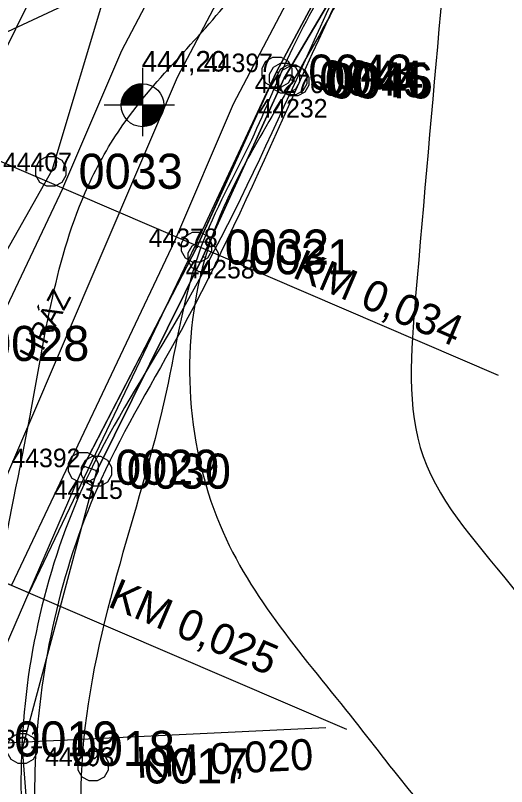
# Model space of a CAD drawing. Extents: x -598521 to -597689, y -1074676 to -1074150.
# Drawn here: x -598484.48 to -598472.57, y -1074197.17 to -1074178.49 of the extents above; entities that cross this region are included whole.
import ezdxf

# ---------------------------------------------------------------- set-up
doc = ezdxf.new("R2010")
doc.units = 0
for name, color, linetype in [('Vrstva 1', 7, 'Continuous'), ('Vrstva 10', 7, 'Continuous'), ('Vrstva 11', 7, 'Continuous'), ('Vrstva 12', 7, 'Continuous'), ('Vrstva 15', 7, 'Continuous'), ('Vrstva 2', 7, 'Continuous'), ('Vrstva 3', 7, 'Continuous'), ('Vrstva 5', 7, 'Continuous'), ('Vrstva 60', 7, 'Continuous'), ('Vrstva 61', 7, 'Continuous'), ('Vrstva 8', 7, 'Continuous')]:
    doc.layers.add(name, color=color, linetype=linetype)

msp = doc.modelspace()

# ---------------------------------------------------------------- linework, layer by layer
at = {"layer": 'Vrstva 1'}
for p, q in [((-598478.16, -1074179.867), (-598478.11, -1074179.867)), ((-598477.98, -1074180.011), (-598477.93, -1074180.011)), ((-598477.799, -1074180.052), (-598477.749, -1074180.052)), ((-598477.751, -1074180.08), (-598477.701, -1074180.08)), ((-598483.642, -1074182.268), (-598483.592, -1074182.268)), ((-598480.11, -1074184.105), (-598480.06, -1074184.105)), ((-598479.949, -1074184.339), (-598479.899, -1074184.339)), ((-598482.856, -1074189.438), (-598482.806, -1074189.438)), ((-598482.536, -1074189.533), (-598482.486, -1074189.533)), ((-598484.337, -1074196.25), (-598484.287, -1074196.25)), ((-598482.62, -1074196.674), (-598482.57, -1074196.674))]:
    msp.add_line(p, q, dxfattribs=at)
for points in [[(-598478.04, -1074179.507), (-598477.87, -1074179.602), (-598477.775, -1074179.772), (-598477.775, -1074179.967), (-598477.87, -1074180.137), (-598478.04, -1074180.232), (-598478.235, -1074180.232), (-598478.405, -1074180.137), (-598478.5, -1074179.967), (-598478.5, -1074179.772), (-598478.405, -1074179.602), (-598478.235, -1074179.507)], [(-598477.86, -1074179.651), (-598477.69, -1074179.746), (-598477.595, -1074179.916), (-598477.595, -1074180.111), (-598477.69, -1074180.281), (-598477.86, -1074180.376), (-598478.055, -1074180.376), (-598478.225, -1074180.281), (-598478.32, -1074180.111), (-598478.32, -1074179.916), (-598478.225, -1074179.746), (-598478.055, -1074179.651)], [(-598477.679, -1074179.692), (-598477.509, -1074179.787), (-598477.414, -1074179.957), (-598477.414, -1074180.152), (-598477.509, -1074180.322), (-598477.679, -1074180.417), (-598477.874, -1074180.417), (-598478.044, -1074180.322), (-598478.139, -1074180.152), (-598478.139, -1074179.957), (-598478.044, -1074179.787), (-598477.874, -1074179.692)], [(-598477.631, -1074179.72), (-598477.461, -1074179.815), (-598477.366, -1074179.985), (-598477.366, -1074180.18), (-598477.461, -1074180.35), (-598477.631, -1074180.445), (-598477.826, -1074180.445), (-598477.996, -1074180.35), (-598478.091, -1074180.18), (-598478.091, -1074179.985), (-598477.996, -1074179.815), (-598477.826, -1074179.72)], [(-598483.522, -1074181.908), (-598483.352, -1074182.003), (-598483.257, -1074182.173), (-598483.257, -1074182.368), (-598483.352, -1074182.538), (-598483.522, -1074182.633), (-598483.717, -1074182.633), (-598483.887, -1074182.538), (-598483.982, -1074182.368), (-598483.982, -1074182.173), (-598483.887, -1074182.003), (-598483.717, -1074181.908)], [(-598479.99, -1074183.745), (-598479.82, -1074183.84), (-598479.725, -1074184.01), (-598479.725, -1074184.205), (-598479.82, -1074184.375), (-598479.99, -1074184.47), (-598480.185, -1074184.47), (-598480.355, -1074184.375), (-598480.45, -1074184.205), (-598480.45, -1074184.01), (-598480.355, -1074183.84), (-598480.185, -1074183.745)], [(-598479.829, -1074183.979), (-598479.659, -1074184.074), (-598479.564, -1074184.244), (-598479.564, -1074184.439), (-598479.659, -1074184.609), (-598479.829, -1074184.704), (-598480.024, -1074184.704), (-598480.194, -1074184.609), (-598480.289, -1074184.439), (-598480.289, -1074184.244), (-598480.194, -1074184.074), (-598480.024, -1074183.979)], [(-598482.736, -1074189.078), (-598482.566, -1074189.173), (-598482.471, -1074189.343), (-598482.471, -1074189.538), (-598482.566, -1074189.708), (-598482.736, -1074189.803), (-598482.931, -1074189.803), (-598483.101, -1074189.708), (-598483.196, -1074189.538), (-598483.196, -1074189.343), (-598483.101, -1074189.173), (-598482.931, -1074189.078)], [(-598482.416, -1074189.173), (-598482.246, -1074189.268), (-598482.151, -1074189.438), (-598482.151, -1074189.633), (-598482.246, -1074189.803), (-598482.416, -1074189.898), (-598482.611, -1074189.898), (-598482.781, -1074189.803), (-598482.876, -1074189.633), (-598482.876, -1074189.438), (-598482.781, -1074189.268), (-598482.611, -1074189.173)], [(-598484.217, -1074195.89), (-598484.047, -1074195.985), (-598483.952, -1074196.155), (-598483.952, -1074196.35), (-598484.047, -1074196.52), (-598484.217, -1074196.615), (-598484.412, -1074196.615), (-598484.582, -1074196.52), (-598484.677, -1074196.35), (-598484.677, -1074196.155), (-598484.582, -1074195.985), (-598484.412, -1074195.89)], [(-598482.5, -1074196.314), (-598482.33, -1074196.409), (-598482.235, -1074196.579), (-598482.235, -1074196.774), (-598482.33, -1074196.944), (-598482.5, -1074197.039), (-598482.695, -1074197.039), (-598482.865, -1074196.944), (-598482.96, -1074196.774), (-598482.96, -1074196.579), (-598482.865, -1074196.409), (-598482.695, -1074196.314)]]:
    msp.add_lwpolyline(points, close=True, dxfattribs=at)
at = {"layer": 'Vrstva 10'}
for points in [[(-598484.92, -1074215.734), (-598487.958, -1074208.491), (-598488.57, -1074195.13), (-598485.971, -1074186.446), (-598483.586, -1074182.241), (-598482.242, -1074177.742), (-598479.451, -1074171.782), (-598475.091, -1074167.2), (-598468.639, -1074162.188), (-598465.635, -1074160.81), (-598454.605, -1074159.518), (-598444.717, -1074161.464), (-598440.447, -1074163.564)], [(-598473.175, -1074171.129), (-598470.76, -1074168.97), (-598466.97, -1074166.72), (-598463.696, -1074165.859), (-598453.096, -1074164.71), (-598446.41, -1074166.04), (-598435.079, -1074171.773), (-598423.335, -1074177.929), (-598417.659, -1074181.967), (-598421.519, -1074188.787), (-598425.53, -1074192.947), (-598427.582, -1074193.806), (-598433.533, -1074199.431), (-598451.678, -1074206.463), (-598460.211, -1074206.905), (-598466.89, -1074208.495), (-598478.904, -1074213.937), (-598483.546, -1074205.944), (-598484.31, -1074196.25), (-598482.504, -1074189.522), (-598479.933, -1074184.345), (-598477.96, -1074180.01), (-598476.52, -1074177.56)], [(-598476.61, -1074175.53), (-598476.74, -1074177.23), (-598478.152, -1074179.86), (-598480.08, -1074184.11), (-598482.83, -1074189.414), (-598485.7, -1074196.02), (-598484.778, -1074206.724), (-598481.095, -1074214.938)], [(-598488.57, -1074195.13), (-598487.78, -1074186.27), (-598487.93, -1074180.4), (-598482.242, -1074177.742)]]:
    msp.add_lwpolyline(points, dxfattribs=at)
msp.add_lwpolyline([(-598476.61, -1074175.53), (-598475.978, -1074175.809), (-598476.52, -1074177.56), (-598477.96, -1074180.01), (-598479.933, -1074184.345), (-598482.504, -1074189.522), (-598482.83, -1074189.414), (-598481.455, -1074186.762), (-598480.08, -1074184.11), (-598479.116, -1074181.985), (-598478.152, -1074179.86), (-598476.74, -1074177.23)], close=True, dxfattribs=at)
at = {"layer": 'Vrstva 11'}
for p, q in [((-598483.334, -1074182.678), (-598487.335, -1074191.113)), ((-598480.623, -1074183.964), (-598484.576, -1074192.297))]:
    msp.add_line(p, q, dxfattribs=at)
at = {"layer": 'Vrstva 12'}
for points in [[(-598477.856, -1074175.904), (-598479.108, -1074177.873), (-598481.873, -1074181.144), (-598482.714, -1074182.62), (-598484.125, -1074188.19), (-598485.335, -1074196.141), (-598485.114, -1074200.364), (-598484.5, -1074206.655), (-598482.536, -1074211.254), (-598480.207, -1074214.488), (-598467.793, -1074210.214), (-598459.725, -1074208.727), (-598453.744, -1074207.761), (-598434.045, -1074202.26), (-598426.944, -1074195.607), (-598420.2, -1074189.398), (-598414.755, -1074180.164), (-598419.159, -1074177.729), (-598424.716, -1074175.666), (-598432.261, -1074171.95), (-598446.273, -1074165.334), (-598449.284, -1074163.066), (-598455.078, -1074161.455), (-598458.605, -1074161.801), (-598464.281, -1074162.718), (-598468.112, -1074164.562), (-598472.279, -1074167.706), (-598475.138, -1074168.205), (-598476.252, -1074168.916), (-598476.978, -1074169.714), (-598477.609, -1074175.205), (-598477.856, -1074175.904)], [(-598473.789, -1074172.039), (-598475.746, -1074175.895), (-598480.673, -1074186.045), (-598482.671, -1074189.544), (-598484.328, -1074196.236), (-598484.11, -1074202.306), (-598483.768, -1074206.314), (-598481.225, -1074209.94), (-598467.357, -1074209.735), (-598459.946, -1074208.147), (-598451.72, -1074206.172), (-598433.884, -1074198.944), (-598427.582, -1074193.806), (-598421.589, -1074188.753), (-598417.664, -1074181.613), (-598423.377, -1074177.475), (-598435.653, -1074170.84), (-598446.227, -1074166.125), (-598452.854, -1074164.125), (-598463.523, -1074165.086), (-598467.1, -1074166.52), (-598468.291, -1074167.262), (-598470.683, -1074168.7), (-598473.219, -1074171.071)], [(-598473.789, -1074172.039), (-598475.746, -1074175.895), (-598480.673, -1074186.045), (-598482.671, -1074189.544), (-598484.328, -1074196.236), (-598484.11, -1074202.306), (-598483.768, -1074206.314), (-598481.225, -1074209.94), (-598467.357, -1074209.735), (-598459.946, -1074208.147), (-598451.72, -1074206.172), (-598433.884, -1074198.944), (-598427.582, -1074193.806), (-598421.589, -1074188.753), (-598417.664, -1074181.613), (-598423.377, -1074177.475), (-598435.653, -1074170.84), (-598446.227, -1074166.125), (-598452.854, -1074164.125), (-598463.523, -1074165.086), (-598467.1, -1074166.52), (-598468.291, -1074167.262), (-598470.683, -1074168.7), (-598473.219, -1074171.071)], [(-598473.448, -1074172.233), (-598475.58, -1074175.922), (-598480.465, -1074186.125), (-598482.4, -1074189.73), (-598483.981, -1074196.229), (-598483.886, -1074202.253), (-598483.546, -1074205.944), (-598480.979, -1074209.161), (-598475.137, -1074210.074), (-598467.043, -1074208.93), (-598460.057, -1074207.659), (-598451.873, -1074205.694), (-598431.777, -1074196.461), (-598429.106, -1074194.199), (-598419.867, -1074184.797), (-598419.874, -1074181.816), (-598423.69, -1074178.164), (-598435.572, -1074171.16), (-598446.402, -1074166.594), (-598452.796, -1074164.414), (-598463.35, -1074165.396), (-598466.975, -1074166.935), (-598468.113, -1074167.583), (-598470.593, -1074168.979), (-598472.889, -1074171.361)], [(-598473.776, -1074172.057), (-598475.787, -1074175.805), (-598476.637, -1074177.247), (-598477.762, -1074179.285), (-598478.759, -1074181.512), (-598479.981, -1074184.111), (-598480.826, -1074187.623), (-598482.872, -1074196.644), (-598480.884, -1074204.447), (-598462.299, -1074205.951), (-598457.621, -1074205.244), (-598448.6, -1074200.236), (-598431.135, -1074190.052), (-598425.671, -1074182.345), (-598436.64, -1074172.436), (-598453.171, -1074165.178), (-598463.86, -1074166.401), (-598467.05, -1074166.63), (-598468.622, -1074167.548), (-598470.002, -1074168.369), (-598470.796, -1074168.897), (-598473.201, -1074171.085)], [(-598473.564, -1074171.726), (-598473.767, -1074172.307), (-598475.013, -1074174.979), (-598476.349, -1074177.568), (-598477.741, -1074180.061), (-598479.834, -1074184.216), (-598479.518, -1074190.843), (-598476.249, -1074195.591), (-598473.028, -1074199.147), (-598469.83, -1074200.65), (-598462.577, -1074200.936), (-598459.26, -1074200.435), (-598452.126, -1074196.474), (-598447.568, -1074189.388), (-598439.169, -1074180.177), (-598437.559, -1074177.648), (-598452.167, -1074170.925), (-598460.9, -1074168.205), (-598465.816, -1074168.205), (-598470.342, -1074169.319), (-598472.087, -1074170.367), (-598473.313, -1074171.425)], [(-598473.564, -1074171.726), (-598474.777, -1074185.291), (-598474.591, -1074189.181), (-598472.32, -1074192.481), (-598469.994, -1074195.048), (-598468.62, -1074195.694), (-598462.854, -1074195.921), (-598460.899, -1074195.626), (-598455.651, -1074192.713), (-598451.546, -1074186.329), (-598444.854, -1074179.795), (-598453.963, -1074175.603), (-598461.661, -1074173.205), (-598473.313, -1074171.425)]]:
    msp.add_spline(points, degree=3, dxfattribs=at)
at = {"layer": 'Vrstva 15'}
for p, q in [((-598472.766, -1074187.213), (-598491.144, -1074179.325)), ((-598476.447, -1074195.791), (-598494.826, -1074187.903)), ((-598476.953, -1074195.75), (-598496.93, -1074196.706))]:
    msp.add_line(p, q, dxfattribs=at)
at = {"layer": 'Vrstva 5'}
for points in [[(-598483.334, -1074182.678), (-598481.903, -1074179.345), (-598476.466, -1074169.022), (-598468.916, -1074163.289), (-598464.703, -1074161.11), (-598455.714, -1074160.021)], [(-598482.963, -1074215.515), (-598486.401, -1074207.525), (-598486.999, -1074195.022), (-598480.548, -1074179.991), (-598475.294, -1074170.015), (-598468.112, -1074164.562), (-598464.254, -1074162.567), (-598455.078, -1074161.455), (-598445.366, -1074162.766), (-598432.996, -1074169.084), (-598417.866, -1074175.801), (-598412.373, -1074178.959)], [(-598480.641, -1074184.01), (-598479.193, -1074180.638), (-598474.122, -1074171.009), (-598467.307, -1074165.835), (-598463.805, -1074164.023), (-598455.361, -1074163)]]:
    msp.add_lwpolyline(points, dxfattribs=at)
at = {"layer": 'Vrstva 60'}
msp.add_lwpolyline([(-598480.179, -1074184.202), (-598480.117, -1074184.058)], dxfattribs=at)
at = {"layer": 'Vrstva 61'}
msp.add_lwpolyline([(-598485.86, -1074181.592), (-598487.335, -1074191.113), (-598484.15, -1074192.479), (-598480.117, -1074184.058), (-598478.152, -1074179.86), (-598476.74, -1074177.23), (-598476.61, -1074175.53), (-598476.12, -1074174.39), (-598475.294, -1074173.013), (-598474.79, -1074172.185), (-598474.564, -1074171.737), (-598475.58, -1074171.07), (-598474.774, -1074169.84), (-598473.651, -1074170.579), (-598471.036, -1074168.831), (-598467.081, -1074166.5), (-598463.394, -1074164.678), (-598455.303, -1074163.295), (-598452.559, -1074163.532), (-598452.084, -1074160.017), (-598455.796, -1074159.225), (-598465.664, -1074160.29), (-598478.074, -1074165.91)], close=True, dxfattribs=at)
at = {"layer": 'Vrstva 8'}
for p, q in [((-598481.398, -1074179.761), (-598481.398, -1074181.416)), ((-598481.402, -1074180.335), (-598481.794, -1074180.335)), ((-598481.402, -1074180.33), (-598481.789, -1074180.33)), ((-598481.402, -1074180.325), (-598481.785, -1074180.325)), ((-598481.402, -1074180.32), (-598481.78, -1074180.32)), ((-598481.402, -1074180.315), (-598481.775, -1074180.315)), ((-598481.402, -1074180.31), (-598481.771, -1074180.31)), ((-598481.402, -1074180.305), (-598481.766, -1074180.305)), ((-598481.402, -1074180.3), (-598481.762, -1074180.3)), ((-598481.402, -1074180.295), (-598481.757, -1074180.295)), ((-598481.402, -1074180.29), (-598481.753, -1074180.29)), ((-598481.402, -1074180.285), (-598481.747, -1074180.285)), ((-598481.402, -1074180.28), (-598481.741, -1074180.28)), ((-598481.402, -1074180.275), (-598481.734, -1074180.275)), ((-598481.402, -1074180.27), (-598481.728, -1074180.27)), ((-598481.402, -1074180.265), (-598481.722, -1074180.265)), ((-598481.402, -1074180.26), (-598481.715, -1074180.26)), ((-598481.402, -1074180.255), (-598481.709, -1074180.255)), ((-598481.402, -1074180.25), (-598481.702, -1074180.25)), ((-598481.402, -1074180.245), (-598481.696, -1074180.245)), ((-598481.402, -1074180.24), (-598481.69, -1074180.24)), ((-598481.402, -1074180.235), (-598481.683, -1074180.235)), ((-598481.402, -1074180.23), (-598481.677, -1074180.23)), ((-598481.402, -1074180.225), (-598481.67, -1074180.225)), ((-598481.402, -1074180.22), (-598481.664, -1074180.22)), ((-598481.402, -1074180.215), (-598481.658, -1074180.215)), ((-598481.402, -1074180.21), (-598481.651, -1074180.21)), ((-598481.402, -1074180.205), (-598481.64, -1074180.205)), ((-598481.402, -1074180.2), (-598481.627, -1074180.2)), ((-598481.402, -1074180.195), (-598481.613, -1074180.195)), ((-598481.402, -1074180.19), (-598481.599, -1074180.19)), ((-598481.402, -1074180.185), (-598481.585, -1074180.185)), ((-598481.402, -1074180.18), (-598481.572, -1074180.18)), ((-598481.402, -1074180.175), (-598481.558, -1074180.175)), ((-598481.402, -1074180.17), (-598481.537, -1074180.17)), ((-598481.402, -1074180.165), (-598481.516, -1074180.165)), ((-598481.402, -1074180.16), (-598481.495, -1074180.16)), ((-598481.402, -1074180.155), (-598481.474, -1074180.155)), ((-598481.402, -1074180.52), (-598481.897, -1074180.52)), ((-598481.402, -1074180.515), (-598481.896, -1074180.515)), ((-598481.402, -1074180.51), (-598481.895, -1074180.51)), ((-598481.402, -1074180.5), (-598481.894, -1074180.5)), ((-598481.402, -1074180.505), (-598481.894, -1074180.505)), ((-598481.402, -1074180.495), (-598481.893, -1074180.495)), ((-598481.402, -1074180.49), (-598481.892, -1074180.49)), ((-598481.402, -1074180.485), (-598481.89, -1074180.485)), ((-598481.402, -1074180.48), (-598481.888, -1074180.48)), ((-598481.402, -1074180.475), (-598481.885, -1074180.475)), ((-598481.402, -1074180.47), (-598481.882, -1074180.47)), ((-598481.402, -1074180.465), (-598481.88, -1074180.465)), ((-598481.402, -1074180.46), (-598481.877, -1074180.46)), ((-598481.402, -1074180.455), (-598481.874, -1074180.455)), ((-598481.402, -1074180.45), (-598481.872, -1074180.45)), ((-598481.402, -1074180.445), (-598481.869, -1074180.445)), ((-598481.402, -1074180.44), (-598481.866, -1074180.44)), ((-598481.402, -1074180.435), (-598481.864, -1074180.435)), ((-598481.402, -1074180.43), (-598481.861, -1074180.43)), ((-598481.402, -1074180.425), (-598481.858, -1074180.425)), ((-598481.402, -1074180.42), (-598481.856, -1074180.42)), ((-598481.402, -1074180.415), (-598481.853, -1074180.415)), ((-598481.402, -1074180.41), (-598481.851, -1074180.41)), ((-598481.402, -1074180.405), (-598481.848, -1074180.405)), ((-598481.402, -1074180.4), (-598481.845, -1074180.4)), ((-598481.402, -1074180.395), (-598481.843, -1074180.395)), ((-598481.402, -1074180.39), (-598481.84, -1074180.39)), ((-598481.402, -1074180.385), (-598481.837, -1074180.385)), ((-598481.402, -1074180.38), (-598481.835, -1074180.38)), ((-598481.402, -1074180.375), (-598481.831, -1074180.375)), ((-598481.402, -1074180.37), (-598481.826, -1074180.37)), ((-598481.402, -1074180.365), (-598481.821, -1074180.365)), ((-598481.402, -1074180.36), (-598481.817, -1074180.36)), ((-598481.402, -1074180.355), (-598481.812, -1074180.355)), ((-598481.402, -1074180.35), (-598481.808, -1074180.35)), ((-598481.402, -1074180.345), (-598481.803, -1074180.345)), ((-598481.402, -1074180.34), (-598481.798, -1074180.34)), ((-598480.626, -1074180.669), (-598482.327, -1074180.669)), ((-598481.402, -1074180.665), (-598481.917, -1074180.665)), ((-598481.402, -1074180.66), (-598481.916, -1074180.66)), ((-598481.402, -1074180.65), (-598481.915, -1074180.65)), ((-598481.402, -1074180.655), (-598481.915, -1074180.655)), ((-598481.402, -1074180.64), (-598481.914, -1074180.64)), ((-598481.402, -1074180.645), (-598481.914, -1074180.645)), ((-598481.402, -1074180.635), (-598481.913, -1074180.635)), ((-598481.402, -1074180.625), (-598481.912, -1074180.625)), ((-598481.402, -1074180.63), (-598481.912, -1074180.63)), ((-598481.402, -1074180.62), (-598481.911, -1074180.62)), ((-598481.402, -1074180.61), (-598481.91, -1074180.61)), ((-598481.402, -1074180.615), (-598481.91, -1074180.615)), ((-598481.402, -1074180.6), (-598481.909, -1074180.6)), ((-598481.402, -1074180.605), (-598481.909, -1074180.605)), ((-598481.402, -1074180.595), (-598481.908, -1074180.595)), ((-598481.402, -1074180.585), (-598481.907, -1074180.585)), ((-598481.402, -1074180.59), (-598481.907, -1074180.59)), ((-598481.402, -1074180.58), (-598481.906, -1074180.58)), ((-598481.402, -1074180.575), (-598481.905, -1074180.575)), ((-598481.402, -1074180.565), (-598481.904, -1074180.565)), ((-598481.402, -1074180.57), (-598481.904, -1074180.57)), ((-598481.402, -1074180.56), (-598481.903, -1074180.56)), ((-598481.402, -1074180.555), (-598481.902, -1074180.555)), ((-598481.402, -1074180.545), (-598481.901, -1074180.545)), ((-598481.402, -1074180.55), (-598481.901, -1074180.55)), ((-598481.402, -1074180.54), (-598481.9, -1074180.54)), ((-598481.402, -1074180.535), (-598481.899, -1074180.535)), ((-598481.402, -1074180.525), (-598481.898, -1074180.525)), ((-598481.402, -1074180.53), (-598481.898, -1074180.53)), ((-598480.878, -1074180.709), (-598481.399, -1074180.709)), ((-598480.876, -1074180.674), (-598481.398, -1074180.674)), ((-598480.876, -1074180.679), (-598481.398, -1074180.679)), ((-598480.877, -1074180.684), (-598481.398, -1074180.684)), ((-598480.877, -1074180.689), (-598481.398, -1074180.689)), ((-598480.877, -1074180.694), (-598481.398, -1074180.694)), ((-598480.877, -1074180.699), (-598481.398, -1074180.699)), ((-598480.878, -1074180.704), (-598481.398, -1074180.704)), ((-598480.911, -1074180.854), (-598481.4, -1074180.854)), ((-598480.913, -1074180.859), (-598481.4, -1074180.859)), ((-598480.914, -1074180.864), (-598481.4, -1074180.864)), ((-598480.915, -1074180.869), (-598481.4, -1074180.869)), ((-598480.917, -1074180.874), (-598481.4, -1074180.874)), ((-598480.918, -1074180.879), (-598481.4, -1074180.879)), ((-598480.92, -1074180.884), (-598481.4, -1074180.884)), ((-598480.923, -1074180.889), (-598481.4, -1074180.889)), ((-598480.927, -1074180.894), (-598481.4, -1074180.894)), ((-598480.878, -1074180.714), (-598481.399, -1074180.714)), ((-598480.879, -1074180.719), (-598481.399, -1074180.719)), ((-598480.879, -1074180.724), (-598481.399, -1074180.724)), ((-598480.879, -1074180.729), (-598481.399, -1074180.729)), ((-598480.879, -1074180.734), (-598481.399, -1074180.734)), ((-598480.88, -1074180.739), (-598481.399, -1074180.739)), ((-598480.88, -1074180.744), (-598481.399, -1074180.744)), ((-598480.882, -1074180.749), (-598481.399, -1074180.749)), ((-598480.883, -1074180.754), (-598481.399, -1074180.754)), ((-598480.885, -1074180.759), (-598481.399, -1074180.759)), ((-598480.886, -1074180.764), (-598481.399, -1074180.764)), ((-598480.887, -1074180.769), (-598481.399, -1074180.769)), ((-598480.889, -1074180.774), (-598481.399, -1074180.774)), ((-598480.89, -1074180.779), (-598481.399, -1074180.779)), ((-598480.892, -1074180.784), (-598481.399, -1074180.784)), ((-598480.893, -1074180.789), (-598481.399, -1074180.789)), ((-598480.894, -1074180.794), (-598481.399, -1074180.794)), ((-598480.896, -1074180.799), (-598481.399, -1074180.799)), ((-598480.897, -1074180.804), (-598481.399, -1074180.804)), ((-598480.898, -1074180.809), (-598481.399, -1074180.809)), ((-598480.9, -1074180.814), (-598481.399, -1074180.814)), ((-598480.901, -1074180.819), (-598481.399, -1074180.819)), ((-598480.903, -1074180.824), (-598481.399, -1074180.824)), ((-598480.904, -1074180.829), (-598481.399, -1074180.829)), ((-598480.905, -1074180.834), (-598481.399, -1074180.834)), ((-598480.907, -1074180.839), (-598481.399, -1074180.839)), ((-598480.908, -1074180.844), (-598481.399, -1074180.844)), ((-598480.91, -1074180.849), (-598481.399, -1074180.849)), ((-598481.01, -1074181.004), (-598481.401, -1074181.004)), ((-598481.014, -1074181.009), (-598481.401, -1074181.009)), ((-598481.019, -1074181.014), (-598481.401, -1074181.014)), ((-598481.024, -1074181.019), (-598481.401, -1074181.019)), ((-598481.028, -1074181.024), (-598481.401, -1074181.024)), ((-598481.033, -1074181.029), (-598481.401, -1074181.029)), ((-598481.038, -1074181.034), (-598481.401, -1074181.034)), ((-598481.043, -1074181.039), (-598481.401, -1074181.039)), ((-598481.047, -1074181.044), (-598481.401, -1074181.044)), ((-598481.052, -1074181.049), (-598481.401, -1074181.049)), ((-598481.056, -1074181.054), (-598481.401, -1074181.054)), ((-598481.061, -1074181.059), (-598481.401, -1074181.059)), ((-598481.066, -1074181.064), (-598481.401, -1074181.064)), ((-598481.07, -1074181.069), (-598481.401, -1074181.069)), ((-598481.075, -1074181.074), (-598481.401, -1074181.074)), ((-598481.08, -1074181.079), (-598481.401, -1074181.079)), ((-598480.93, -1074180.899), (-598481.4, -1074180.899)), ((-598480.933, -1074180.904), (-598481.4, -1074180.904)), ((-598480.937, -1074180.909), (-598481.4, -1074180.909)), ((-598480.94, -1074180.914), (-598481.4, -1074180.914)), ((-598480.943, -1074180.919), (-598481.4, -1074180.919)), ((-598480.947, -1074180.924), (-598481.4, -1074180.924)), ((-598480.95, -1074180.929), (-598481.4, -1074180.929)), ((-598480.954, -1074180.934), (-598481.4, -1074180.934)), ((-598480.957, -1074180.939), (-598481.4, -1074180.939)), ((-598480.96, -1074180.944), (-598481.4, -1074180.944)), ((-598480.964, -1074180.949), (-598481.4, -1074180.949)), ((-598480.967, -1074180.954), (-598481.4, -1074180.954)), ((-598480.97, -1074180.959), (-598481.4, -1074180.959)), ((-598480.974, -1074180.964), (-598481.4, -1074180.964)), ((-598480.977, -1074180.969), (-598481.4, -1074180.969)), ((-598480.982, -1074180.974), (-598481.4, -1074180.974)), ((-598480.986, -1074180.979), (-598481.4, -1074180.979)), ((-598480.991, -1074180.984), (-598481.4, -1074180.984)), ((-598480.996, -1074180.989), (-598481.4, -1074180.989)), ((-598481, -1074180.994), (-598481.4, -1074180.994)), ((-598481.005, -1074180.999), (-598481.4, -1074180.999)), ((-598481.204, -1074181.149), (-598481.402, -1074181.149)), ((-598481.219, -1074181.154), (-598481.402, -1074181.154)), ((-598481.239, -1074181.159), (-598481.402, -1074181.159)), ((-598481.258, -1074181.164), (-598481.402, -1074181.164)), ((-598481.278, -1074181.169), (-598481.402, -1074181.169)), ((-598481.299, -1074181.174), (-598481.402, -1074181.174)), ((-598481.327, -1074181.179), (-598481.402, -1074181.179)), ((-598481.355, -1074181.184), (-598481.402, -1074181.184)), ((-598481.084, -1074181.084), (-598481.401, -1074181.084)), ((-598481.091, -1074181.089), (-598481.401, -1074181.089)), ((-598481.1, -1074181.094), (-598481.401, -1074181.094)), ((-598481.108, -1074181.099), (-598481.401, -1074181.099)), ((-598481.117, -1074181.104), (-598481.401, -1074181.104)), ((-598481.125, -1074181.109), (-598481.401, -1074181.109)), ((-598481.134, -1074181.114), (-598481.401, -1074181.114)), ((-598481.142, -1074181.119), (-598481.401, -1074181.119)), ((-598481.151, -1074181.124), (-598481.401, -1074181.124)), ((-598481.162, -1074181.129), (-598481.401, -1074181.129)), ((-598481.173, -1074181.134), (-598481.401, -1074181.134)), ((-598481.183, -1074181.139), (-598481.401, -1074181.139)), ((-598481.194, -1074181.144), (-598481.401, -1074181.144))]:
    msp.add_line(p, q, dxfattribs=at)
msp.add_circle((-598481.398, -1074180.669), 0.52, dxfattribs=at)

# ---------------------------------------------------------------- texts
at = {"layer": 'Vrstva 10'}
msp.add_text('HRÁZ', height=0.5, rotation=62.3052, dxfattribs=at).set_placement((-598483.962, -1074186.919))
at = {"layer": 'Vrstva 11'}
msp.add_text('444,20', height=0.5, dxfattribs=at).set_placement((-598481.415, -1074179.854))
at = {"layer": 'Vrstva 15'}
for s, rotation, p in [('KM 0,034', 336.7708, (-598477.789, -1074184.83)), ('KM 0,025', 336.7708, (-598482.269, -1074192.801)), ('KM 0,020', 2.7408, (-598481.531, -1074196.968))]:
    msp.add_text(s, height=0.75, rotation=rotation, dxfattribs=at).set_placement(p)
at = {"layer": 'Vrstva 2'}
for s, p in [('0043', (-598477.379, -1074180.292)), ('0044', (-598477.113, -1074180.436)), ('0045', (-598476.978, -1074180.477)), ('0046', (-598476.883, -1074180.505)), ('0033', (-598482.949, -1074182.693)), ('0032', (-598479.403, -1074184.53)), ('0031', (-598478.82, -1074184.764)), ('0028', (-598485.216, -1074186.864)), ('0029', (-598482.062, -1074189.863)), ('0030', (-598481.782, -1074189.958)), ('0019', (-598484.509, -1074196.445)), ('0018', (-598483.141, -1074196.675)), ('0017', (-598481.364, -1074197.099))]:
    msp.add_text(s, height=0.85, dxfattribs=at).set_placement(p)
at = {"layer": 'Vrstva 3'}
for s, p in [('44397', (-598479.909, -1074179.867)), ('44276', (-598478.678, -1074180.376)), ('44232', (-598478.586, -1074180.967)), ('44407', (-598484.782, -1074182.268)), ('44378', (-598481.249, -1074184.105)), ('44258', (-598480.353, -1074184.865)), ('44392', (-598484.577, -1074189.438)), ('44315', (-598483.55, -1074190.206)), ('44351', (-598485.476, -1074196.25)), ('44293', (-598483.76, -1074196.674))]:
    msp.add_text(s, height=0.45, dxfattribs=at).set_placement(p)

doc.saveas('drawing.dxf')
